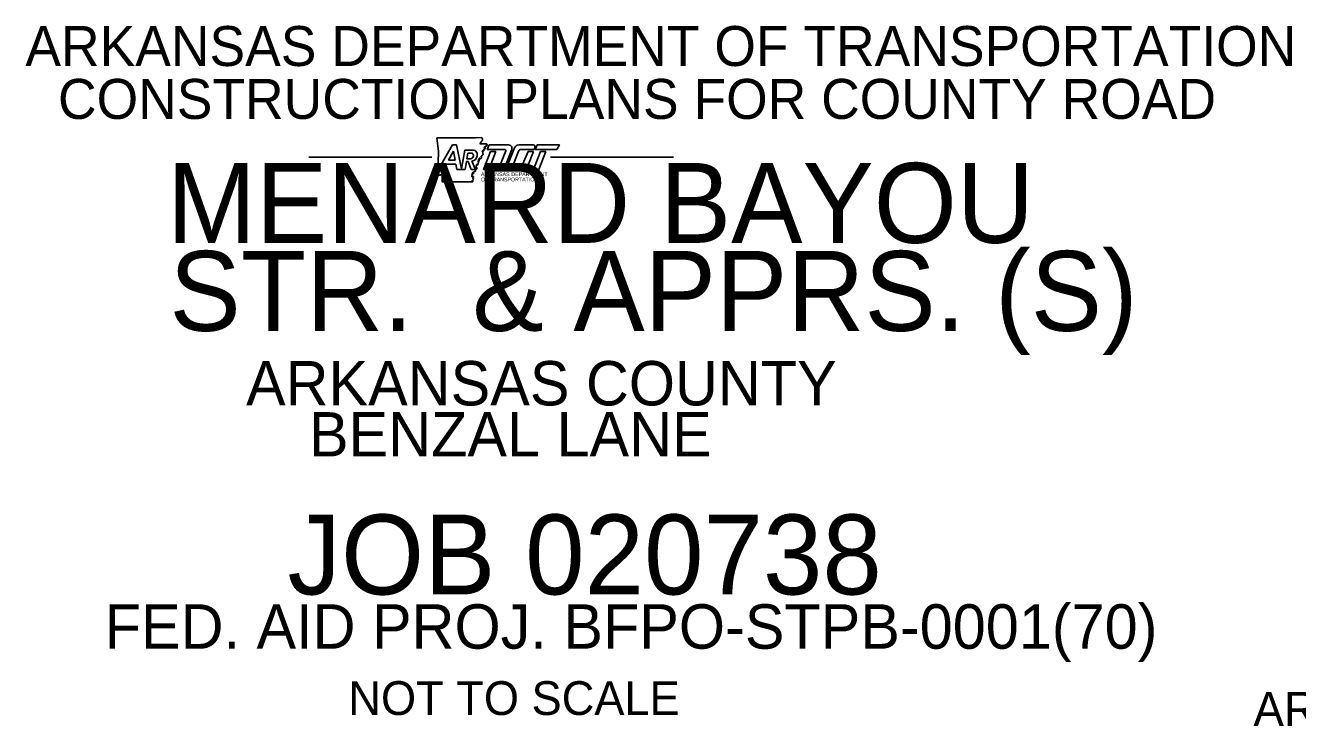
# Model space of a CAD drawing. Extents: x -28335 to 1228743, y -22428 to 152440.
# Drawn here: x -5314 to 23831, y 4514 to 20579 of the extents above; entities that cross this region are included whole.
import ezdxf

# ---------------------------------------------------------------- set-up
doc = ezdxf.new("R2010")
doc.units = 0
for name, color, linetype in [('2', 7, 'Continuous'), ('Default', 7, 'Continuous'), ('R_Border Notes', 7, 'Continuous'), ('R_Draft', 7, 'Continuous')]:
    doc.layers.add(name, color=color, linetype=linetype)

msp = doc.modelspace()

# ---------------------------------------------------------------- linework, layer by layer
at = {"layer": 'R_Border Notes'}
for p, q in [((4153, 17284), (4467, 17840)), ((4467, 17840), (4562, 17840)), ((4562, 17840), (4676, 17291)), ((5241, 17870), (5098, 17863)), ((5308, 17842), (5261, 17737)), ((5755, 17842), (5308, 17842)), ((6320, 17842), (5987, 17842)), ((6346, 17746), (6360, 17785)), ((6407, 17845), (6364, 17733)), ((6924, 17844), (6407, 17845)), ((6860, 17733), (6924, 17844)), ((4492, 17697), (4377, 17494)), ((4377, 17494), (4531, 17494)), ((4531, 17494), (4492, 17697)), ((4676, 17291), (4754, 17721)), ((4754, 17721), (4952, 17721)), ((4822, 17650), (4802, 17525)), ((4802, 17525), (4882, 17525)), ((4910, 17650), (4822, 17650)), ((4950, 17594), (4950, 17610)), ((5034, 17650), (5034, 17588)), ((5261, 17737), (5667, 17737)), ((5460, 17690), (5340, 17690)), ((5350, 17394), (5460, 17690)), ((5689, 17705), (5588, 17440)), ((5699, 17409), (5827, 17737)), ((5888, 17773), (5726, 17352)), ((5876, 17420), (5989, 17713)), ((6023, 17737), (6333, 17737)), ((6202, 17690), (6085, 17410)), ((6197, 17362), (6323, 17690)), ((6323, 17690), (6202, 17690)), ((6485, 17691), (6327, 17280)), ((6364, 17733), (6860, 17733)), ((6449, 17280), (6612, 17691)), ((6612, 17691), (6485, 17691)), ((4262, 17284), (4153, 17284)), ((4547, 17404), (4324, 17404)), ((4571, 17282), (4547, 17404)), ((4675, 17282), (4571, 17282)), ((4759, 17282), (4675, 17282)), ((4790, 17461), (4759, 17282)), ((4832, 17461), (4790, 17461)), ((4901, 17282), (4832, 17461)), ((4994, 17282), (4901, 17282)), ((4916, 17470), (4994, 17282)), ((5517, 17392), (5352, 17392)), ((5774, 17282), (6080, 17282)), ((6058, 17392), (5892, 17392)), ((6327, 17280), (6449, 17280))]:
    msp.add_line(p, q, dxfattribs=at)
for points in [[(5143, 18010), (4997, 18007), (4681, 18002), (4414, 18001), (4110, 18002)], [(4110, 18002), (4149, 17688), (4132, 17177)], [(5340, 17690), (5183, 17282), (5515, 17282)], [(4324, 17404), (4262, 17284), (4262, 17283), (4262, 17284)], [(4236, 17147), (4236, 16995), (4926, 16993)]]:
    msp.add_lwpolyline(points, dxfattribs=at)
for centre, radius, start, end in [((5755, 17765), 77, 338.81, 90.0244), ((5987, 17735), 107, 90.0159, 159.0252), ((6320, 17799), 42.5, 339.9797, 90.0159), ((4882, 17593), 68.4, 270, 0.8203), ((4910, 17610), 40, 0, 90.2531), ((4906, 17598), 128, 274.233, 355.6275), ((4942, 17627), 94.7, 14.1904, 83.9934), ((5667, 17714), 23.5, 339.1692, 89.9954), ((6023, 17700), 37.2, 90.0183, 159.0781), ((6333, 17750), 13.1, 270.0183, 339.9797), ((5352, 17394), 1.77, 159.6445, 270.0081), ((5515, 17480), 198, 269.9471, 338.81), ((5517, 17467), 75.1, 270.0081, 339.1692), ((5774, 17334), 51.6, 159.0252, 269.9823), ((5891, 17410), 18, 146.4856, 270.228), ((6058, 17421), 29.4, 270.0618, 337.3322), ((6080, 17407), 125, 269.9823, 339.0187)]:
    msp.add_arc(centre, radius, start, end, dxfattribs=at)
for points in [[(5098, 17863), (5103, 17875), (5104, 17880), (5108, 17886), (5110, 17891), (5115, 17896), (5118, 17900), (5122, 17904), (5124, 17910), (5128, 17915), (5132, 17919), (5137, 17924), (5142, 17929), (5145, 17933), (5149, 17937), (5153, 17940), (5158, 17945), (5159, 17951), (5160, 17957), (5160, 17964), (5161, 17971), (5160, 17977), (5156, 17983), (5150, 17986), (5147, 17990), (5146, 17998), (5144, 18002), (5143, 18010)], [(5065, 17452), (5064, 17453), (5059, 17458), (5059, 17466), (5059, 17472), (5060, 17478), (5063, 17482), (5066, 17478), (5068, 17474), (5069, 17469), (5073, 17467), (5078, 17468), (5081, 17473), (5083, 17478), (5083, 17483), (5081, 17487), (5076, 17488), (5070, 17489), (5067, 17492), (5069, 17500), (5069, 17505), (5069, 17511), (5073, 17513), (5075, 17510), (5074, 17505), (5074, 17500), (5081, 17497), (5085, 17502)], [(5085, 17502), (5086, 17511), (5087, 17516), (5086, 17525), (5084, 17531), (5084, 17537), (5088, 17539), (5092, 17538), (5096, 17535), (5100, 17530), (5104, 17529), (5108, 17531), (5112, 17531), (5117, 17531), (5121, 17530), (5124, 17532), (5126, 17536), (5127, 17542), (5131, 17545), (5133, 17550), (5134, 17556), (5133, 17561), (5130, 17567), (5126, 17572), (5126, 17579), (5129, 17583), (5135, 17584), (5136, 17585)], [(5136, 17585), (5141, 17585), (5145, 17591), (5147, 17596), (5149, 17600), (5152, 17606), (5154, 17611), (5158, 17615), (5163, 17614), (5168, 17613), (5172, 17614), (5175, 17620), (5174, 17625), (5172, 17631), (5171, 17636), (5170, 17644), (5167, 17647), (5161, 17650), (5156, 17655), (5152, 17659), (5158, 17663), (5164, 17666), (5163, 17672), (5164, 17678), (5168, 17684), (5167, 17689)], [(4915, 17188), (4917, 17192), (4921, 17193), (4927, 17191), (4933, 17188), (4938, 17184), (4945, 17181), (4950, 17184), (4954, 17189), (4952, 17196), (4946, 17197), (4941, 17197), (4935, 17203), (4935, 17212), (4939, 17213), (4945, 17216), (4949, 17217), (4954, 17215), (4961, 17213), (4964, 17215), (4969, 17222), (4970, 17228), (4971, 17233), (4986, 17232), (4995, 17237), (4995, 17247), (4996, 17254)], [(4996, 17254), (4998, 17260), (4998, 17265), (4999, 17267), (5000, 17272), (5005, 17274), (5011, 17282), (5012, 17294), (5030, 17299), (5031, 17307), (5032, 17313), (5026, 17320), (5019, 17323), (5012, 17338), (5013, 17353), (5008, 17362), (5012, 17364), (5013, 17364)], [(5013, 17364), (5018, 17364), (5024, 17368), (5024, 17369), (5025, 17375), (5024, 17380), (5022, 17387), (5023, 17390), (5027, 17390), (5032, 17388), (5033, 17385), (5033, 17382), (5034, 17379), (5036, 17377), (5039, 17377), (5043, 17382), (5044, 17386), (5045, 17392), (5048, 17395), (5051, 17397), (5056, 17402), (5058, 17407), (5060, 17415), (5059, 17423), (5061, 17430), (5062, 17436), (5066, 17442), (5067, 17447), (5065, 17452)], [(4132, 17177), (4137, 17170), (4139, 17165), (4143, 17159), (4147, 17156), (4153, 17155), (4154, 17149), (4159, 17148), (4164, 17150), (4170, 17148), (4177, 17152), (4181, 17151), (4186, 17154), (4190, 17150), (4197, 17153), (4204, 17157), (4210, 17153), (4216, 17153), (4222, 17152), (4228, 17152), (4233, 17149), (4236, 17147)], [(4947, 17117), (4946, 17116), (4943, 17113), (4941, 17110), (4938, 17107), (4936, 17104), (4931, 17102), (4924, 17101), (4921, 17103), (4920, 17108), (4924, 17112), (4929, 17114), (4933, 17116), (4936, 17121), (4934, 17127), (4929, 17130), (4925, 17127), (4923, 17123), (4921, 17120), (4917, 17118), (4914, 17117), (4912, 17119), (4912, 17124), (4915, 17131), (4917, 17136), (4917, 17141), (4915, 17149), (4913, 17155), (4914, 17156), (4918, 17158), (4924, 17160), (4927, 17161), (4928, 17166), (4924, 17172), (4919, 17177), (4916, 17184), (4915, 17188)], [(4926, 16993), (4934, 16997), (4937, 17001), (4937, 17004), (4935, 17009), (4931, 17014), (4928, 17016), (4924, 17021), (4923, 17027), (4927, 17030), (4934, 17029), (4941, 17029), (4944, 17031), (4945, 17036), (4945, 17040), (4945, 17045), (4947, 17052), (4950, 17057), (4954, 17062), (4954, 17067), (4951, 17070), (4946, 17069), (4942, 17068), (4939, 17073), (4937, 17078), (4936, 17086), (4941, 17093), (4945, 17097), (4949, 17102), (4951, 17108), (4952, 17114), (4950, 17117), (4947, 17117)]]:
    msp.add_spline(points, degree=3, dxfattribs=at)
for points in [[(5199, 17777), (5199, 17777), (5199, 17777), (5199, 17778), (5199, 17778), (5200, 17779), (5200, 17780), (5200, 17780), (5200, 17781), (5200, 17781), (5200, 17782), (5200, 17783), (5200, 17783), (5200, 17784), (5199, 17784), (5199, 17785), (5199, 17785), (5199, 17786), (5199, 17787), (5199, 17787), (5199, 17788), (5199, 17788), (5199, 17789), (5199, 17789), (5199, 17790), (5199, 17790), (5200, 17791), (5200, 17791), (5200, 17792), (5201, 17793), (5202, 17793), (5202, 17794), (5202, 17794), (5202, 17794), (5202, 17794), (5203, 17794), (5203, 17794), (5203, 17795), (5204, 17795), (5204, 17795), (5205, 17795), (5205, 17796), (5206, 17796), (5206, 17796), (5207, 17796), (5208, 17796), (5209, 17796), (5209, 17797), (5210, 17797), (5211, 17797), (5212, 17797), (5213, 17797), (5214, 17797), (5214, 17797), (5215, 17797), (5215, 17797), (5216, 17797), (5216, 17797), (5217, 17798), (5217, 17798), (5217, 17798), (5218, 17798), (5218, 17798), (5219, 17798), (5220, 17798), (5221, 17798), (5222, 17799), (5223, 17799), (5224, 17799), (5225, 17800), (5226, 17800), (5227, 17800), (5228, 17800), (5229, 17801), (5230, 17801), (5231, 17801), (5231, 17802), (5231, 17802), (5231, 17802), (5232, 17803), (5232, 17803), (5232, 17803), (5232, 17804), (5232, 17804), (5232, 17805), (5233, 17805), (5233, 17805), (5233, 17806), (5233, 17806), (5234, 17806), (5234, 17807)], [(5234, 17807), (5234, 17807), (5234, 17807), (5234, 17807), (5235, 17807), (5235, 17808), (5235, 17808), (5236, 17809), (5236, 17809), (5237, 17809), (5237, 17810), (5238, 17810), (5238, 17810), (5239, 17811), (5239, 17811), (5240, 17811), (5240, 17811), (5241, 17811), (5241, 17811), (5242, 17812), (5242, 17812), (5243, 17812), (5243, 17812), (5244, 17812), (5244, 17812), (5245, 17813), (5246, 17813), (5247, 17814), (5248, 17814), (5249, 17815), (5250, 17815), (5251, 17815), (5251, 17816), (5251, 17816), (5252, 17817), (5252, 17817), (5252, 17817), (5253, 17818), (5253, 17819), (5253, 17820), (5253, 17820), (5253, 17821), (5253, 17821), (5253, 17822), (5253, 17822), (5253, 17823), (5253, 17823), (5253, 17824), (5253, 17824), (5252, 17824), (5252, 17825), (5252, 17825), (5251, 17826), (5251, 17826), (5250, 17827), (5250, 17827), (5250, 17827), (5249, 17828), (5249, 17828), (5248, 17828), (5248, 17829), (5247, 17829), (5247, 17829), (5246, 17830), (5245, 17831), (5245, 17832), (5244, 17832), (5243, 17833), (5243, 17833), (5243, 17834), (5242, 17834), (5242, 17834), (5242, 17835), (5242, 17835), (5242, 17835), (5242, 17835), (5242, 17835), (5242, 17835), (5242, 17835), (5242, 17836), (5242, 17836), (5242, 17836), (5243, 17836), (5243, 17837), (5244, 17837), (5244, 17837), (5245, 17838), (5245, 17838), (5246, 17838), (5246, 17838), (5247, 17839), (5247, 17839), (5247, 17839), (5247, 17839), (5248, 17839), (5248, 17839), (5248, 17839), (5249, 17839), (5249, 17839), (5250, 17839), (5250, 17839), (5250, 17839), (5251, 17838), (5251, 17838), (5251, 17838), (5251, 17838)], [(5251, 17838), (5251, 17838), (5252, 17838), (5252, 17838), (5253, 17839), (5254, 17839), (5255, 17839), (5256, 17839), (5257, 17839), (5258, 17839), (5258, 17839), (5259, 17839), (5259, 17839), (5259, 17839), (5259, 17839), (5259, 17839), (5260, 17839), (5260, 17839), (5261, 17839), (5261, 17839), (5262, 17839), (5262, 17839), (5263, 17839), (5263, 17840), (5263, 17840), (5264, 17840), (5264, 17840), (5264, 17840), (5264, 17840), (5264, 17840), (5264, 17840), (5264, 17840), (5264, 17841), (5264, 17841), (5264, 17841), (5265, 17841), (5265, 17842), (5265, 17842), (5265, 17842), (5265, 17843), (5265, 17843), (5265, 17844), (5265, 17844), (5264, 17846), (5263, 17847), (5262, 17849), (5261, 17850), (5260, 17852), (5259, 17853), (5258, 17853), (5258, 17854), (5258, 17854), (5257, 17854), (5257, 17854), (5256, 17854), (5256, 17854), (5255, 17854), (5255, 17854), (5255, 17854), (5254, 17854), (5254, 17855), (5252, 17855), (5251, 17856), (5250, 17858), (5250, 17858), (5249, 17859), (5249, 17859), (5249, 17860), (5249, 17860), (5248, 17861), (5248, 17861), (5248, 17862), (5248, 17862), (5247, 17863), (5247, 17863), (5247, 17864), (5247, 17864), (5246, 17864), (5246, 17865), (5246, 17865), (5246, 17865), (5246, 17866), (5245, 17866), (5245, 17867), (5244, 17868), (5244, 17868), (5243, 17869), (5243, 17869), (5242, 17870), (5241, 17870), (5241, 17870)], [(5167, 17689), (5166, 17690), (5166, 17691), (5166, 17692), (5165, 17693), (5165, 17693), (5165, 17693), (5165, 17694), (5164, 17694), (5164, 17694), (5164, 17694), (5164, 17695), (5164, 17695), (5164, 17695), (5163, 17695), (5163, 17695), (5163, 17695), (5162, 17695), (5162, 17695), (5162, 17695), (5162, 17695), (5161, 17695), (5161, 17695), (5161, 17695), (5161, 17694), (5160, 17694), (5160, 17694), (5160, 17693), (5160, 17693), (5160, 17693), (5160, 17692), (5160, 17692), (5160, 17692), (5160, 17691), (5159, 17691), (5159, 17691), (5159, 17690), (5159, 17690), (5158, 17690), (5158, 17690), (5158, 17690), (5158, 17690), (5157, 17690), (5157, 17689), (5157, 17689), (5157, 17689), (5156, 17689), (5156, 17689), (5156, 17689), (5155, 17689), (5155, 17689), (5155, 17689), (5154, 17689), (5154, 17689), (5154, 17690), (5153, 17690), (5153, 17690), (5153, 17690), (5152, 17690), (5152, 17690), (5152, 17691), (5151, 17691), (5151, 17691), (5151, 17691), (5151, 17691), (5151, 17691), (5151, 17691), (5151, 17692), (5151, 17692), (5150, 17692), (5150, 17693), (5150, 17693), (5150, 17694), (5149, 17694), (5149, 17695), (5149, 17695), (5149, 17696), (5150, 17696), (5150, 17697), (5150, 17697), (5150, 17697), (5150, 17698), (5151, 17698), (5151, 17699), (5151, 17699), (5152, 17700), (5152, 17701), (5153, 17701), (5153, 17702), (5154, 17702), (5154, 17703), (5155, 17703), (5155, 17703), (5156, 17704), (5156, 17704), (5157, 17705), (5157, 17705), (5158, 17705), (5158, 17706), (5159, 17706), (5159, 17707), (5160, 17707), (5161, 17708), (5161, 17709), (5162, 17710), (5163, 17710), (5163, 17711), (5164, 17711), (5165, 17712), (5165, 17712), (5165, 17712), (5166, 17713), (5166, 17713), (5166, 17713), (5167, 17713), (5167, 17714), (5168, 17714), (5168, 17714)], [(5168, 17714), (5168, 17714), (5168, 17714), (5168, 17714), (5169, 17714), (5169, 17713), (5170, 17713), (5170, 17713), (5170, 17713), (5171, 17712), (5171, 17712), (5171, 17712), (5171, 17711), (5172, 17711), (5172, 17711), (5172, 17711), (5172, 17710), (5172, 17710), (5172, 17710), (5172, 17709), (5172, 17709), (5172, 17708), (5172, 17708), (5172, 17707), (5173, 17707), (5173, 17706), (5173, 17705), (5173, 17704), (5173, 17703), (5173, 17701), (5173, 17700), (5174, 17699), (5174, 17698), (5174, 17697), (5174, 17696), (5174, 17696), (5175, 17696), (5175, 17696), (5175, 17696), (5175, 17696), (5175, 17696), (5176, 17696), (5176, 17697), (5177, 17697), (5178, 17698), (5178, 17699), (5178, 17699), (5179, 17700), (5179, 17700), (5179, 17701), (5180, 17701), (5180, 17702), (5180, 17702), (5180, 17703), (5181, 17704), (5181, 17704), (5181, 17705), (5181, 17705), (5182, 17707), (5182, 17710), (5183, 17712), (5183, 17713), (5183, 17715), (5183, 17716), (5182, 17718), (5182, 17720), (5181, 17722), (5181, 17724), (5180, 17725), (5180, 17727), (5180, 17727), (5180, 17727), (5180, 17727)], [(5180, 17727), (5180, 17728), (5180, 17728), (5180, 17728), (5180, 17729), (5180, 17729), (5180, 17730), (5181, 17730), (5181, 17731), (5181, 17731), (5181, 17732), (5181, 17732), (5182, 17732), (5182, 17733), (5182, 17733), (5182, 17733), (5182, 17733), (5182, 17734), (5181, 17734), (5181, 17734), (5181, 17735), (5181, 17735), (5181, 17736), (5181, 17736), (5181, 17737), (5181, 17737), (5181, 17737), (5182, 17738), (5182, 17738), (5182, 17738), (5182, 17738), (5182, 17739), (5182, 17739), (5182, 17739), (5183, 17739), (5183, 17740), (5183, 17740), (5184, 17740), (5184, 17740), (5185, 17740), (5185, 17740), (5185, 17740), (5186, 17740), (5187, 17740), (5188, 17739), (5189, 17739), (5191, 17738), (5192, 17738), (5193, 17737), (5194, 17737), (5194, 17737), (5194, 17736), (5195, 17736), (5195, 17735), (5195, 17735), (5195, 17734), (5196, 17734), (5196, 17733), (5196, 17733), (5196, 17733), (5197, 17732), (5198, 17732), (5198, 17732), (5199, 17731), (5200, 17731), (5201, 17731), (5202, 17731), (5203, 17732), (5204, 17732), (5204, 17732), (5205, 17733), (5205, 17733), (5205, 17733), (5206, 17733), (5206, 17733), (5206, 17734), (5206, 17734), (5206, 17734), (5206, 17734), (5207, 17735), (5207, 17737), (5207, 17738), (5206, 17740), (5205, 17741), (5204, 17742), (5204, 17743), (5203, 17743), (5203, 17743), (5203, 17743), (5202, 17744), (5202, 17744), (5202, 17744), (5201, 17744), (5201, 17744), (5201, 17745), (5200, 17745), (5200, 17745)], [(5200, 17745), (5200, 17745), (5200, 17745), (5200, 17745), (5199, 17746), (5199, 17746), (5198, 17747), (5198, 17748), (5198, 17749), (5198, 17749), (5199, 17749), (5199, 17750), (5199, 17750), (5200, 17751), (5200, 17751), (5200, 17751), (5201, 17752), (5202, 17753), (5203, 17753), (5203, 17753), (5204, 17753), (5204, 17754), (5204, 17754), (5205, 17754), (5205, 17754), (5206, 17754), (5206, 17754), (5206, 17754), (5207, 17755), (5207, 17755), (5208, 17755), (5209, 17756), (5211, 17758), (5212, 17759), (5213, 17760), (5213, 17760), (5213, 17760), (5214, 17761), (5214, 17761), (5214, 17762), (5215, 17763), (5216, 17763), (5216, 17764), (5217, 17765), (5217, 17766), (5217, 17766), (5217, 17767), (5217, 17767), (5217, 17768), (5217, 17768), (5217, 17768), (5217, 17769), (5217, 17769), (5216, 17769), (5216, 17769), (5216, 17769), (5216, 17770), (5216, 17770), (5215, 17770), (5215, 17770), (5214, 17770), (5213, 17771), (5212, 17771), (5211, 17771), (5211, 17772), (5210, 17772), (5210, 17772), (5210, 17772), (5209, 17772), (5209, 17772), (5208, 17772), (5208, 17772), (5207, 17772), (5207, 17772), (5206, 17772), (5206, 17772), (5205, 17772), (5205, 17772), (5204, 17772), (5204, 17772), (5203, 17772), (5202, 17772), (5202, 17772), (5201, 17773), (5201, 17773), (5200, 17773), (5200, 17774), (5200, 17774), (5200, 17774), (5200, 17774), (5199, 17775), (5199, 17775), (5199, 17775), (5199, 17775), (5199, 17775), (5199, 17776), (5199, 17776), (5199, 17776), (5199, 17776), (5199, 17777)]]:
    msp.add_open_spline(points, degree=3, dxfattribs=at)
at = {"layer": 'R_Draft'}
for p, q in [((1178, 17562), (3993, 17562)), ((6715, 17562), (9530, 17562))]:
    msp.add_line(p, q, dxfattribs=at)

# ---------------------------------------------------------------- texts
at = {"layer": '2'}
msp.add_text('NOT TO SCALE', height=774.01, dxfattribs=at).set_placement((2084, 4779))
at = {"layer": 'Default'}
for s, height, p in [('MENARD BAYOU ', 1831.35, (-2072, 15597)), ('STR.  & APPRS. (S)', 1831.35, (-2014, 13580)), ('ARKANSAS COUNTY', 1017.41, (-260, 11872)), ('BENZAL LANE', 1017.41, (1182, 10702)), ('JOB 020738', 1831.3, (692, 7541)), ('FED. AID PROJ. BFPO-STPB-0001(70)', 1017.41, (-3497, 6298))]:
    msp.add_text(s, height=height, dxfattribs=at).set_placement(p)
at = {"layer": 'R_Border Notes'}
for s, height, p in [('ARKANSAS', 87.2, (5122, 17126)), ('DEPARTMENT', 87.2, (5819, 17126)), ('OF TRANSPORTATION', 87.23, (5122, 17005))]:
    msp.add_text(s, height=height, dxfattribs=at).set_placement(p)
at = {"layer": 'R_Draft'}
for s, height, p in [('ARKANSAS DEPARTMENT OF TRANSPORTATION', 915.67, (-5316, 19650)), ('CONSTRUCTION PLANS FOR COUNTY ROAD', 915.67, (-4568, 18438)), ('ARKANSAS HIGHWAY DISTRICT 2', 783.39, (22820, 4525))]:
    msp.add_text(s, height=height, dxfattribs=at).set_placement(p)

doc.saveas('drawing.dxf')
